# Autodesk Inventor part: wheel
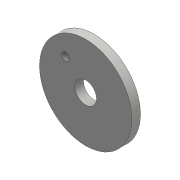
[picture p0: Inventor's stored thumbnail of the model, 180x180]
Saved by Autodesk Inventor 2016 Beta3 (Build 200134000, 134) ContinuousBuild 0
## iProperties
Created: 2016-03
Part Number: wheel
Material: Generic
Document SubType Name: Modeling
Designer: Gaurav
Density: 1 g/cm^3
Appearance: Default
Author: Gaurav
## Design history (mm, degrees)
sketch "Sketch1"
  geometry: C1 r 75 at (0, 0); C2 r 17.5 at (0, 0); 1 further point
  constraints: 2 centre point, 2 coincident
  dimensions: "d0" = 150 diameter of C1; "d3" = 35 diameter of C2
extrude "Extrusion2" new body sketch "Sketch1" distance "d4" = 14; taper "d5" = 0 deg
sketch "Sketch2"
  geometry: C1 r 6.253 at (-32.427, 34.638); 1 further point
  constraints: 1 centre point
extrude "Extrusion3" cut sketch "Sketch2" distance "d6" = 14; taper "d7" = 0 deg
body "Solid2"
